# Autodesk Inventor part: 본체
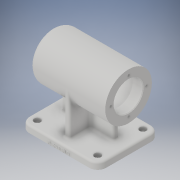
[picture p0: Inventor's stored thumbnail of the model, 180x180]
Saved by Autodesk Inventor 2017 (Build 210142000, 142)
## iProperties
Part Number: 본체
Material: 일반
Document SubType Name: Modeling
Designer: 00-00
Density: 1 g/cm^3
Appearance: 기본값
Author: 00-00
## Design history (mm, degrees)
sketch "스케치1"
  geometry: L1 (-56, 45)-(56, 45); L2 (56, 45)-(56, -45); L3 (56, -45)-(-56, -45); L4 (-56, -45)-(-56, 45); L5 (-56, 45)-(56, -45); L6 (56, 45)-(-56, -45); 1 further point
  constraints: 12 end point, 2 midpoint, 2 parallel, 1 horizontal, 1 perpendicular
  dimensions: "d0" = 112 distance of L2.end L3.end; "d1" = 90 distance of L1.end L2.end
extrude "돌출1" new body sketch "스케치1" distance "d2" = 10; taper "d3" = 0 deg
sketch "스케치2"
  geometry: L1 (0, 45)-(-74, 45); C1 r 34 at (-74, 45)
  constraints: 2 end point, 1 centre point, 1 coincident, 1 horizontal
  dimensions: "d4" = 74 distance of L1.start L1.end; "d5" = 68 diameter of C1
extrude "돌출2" join sketch "스케치2" distance "d6" = 112; taper "d7" = 0 deg
sketch "스케치3"
  geometry: L1 (38, -4)-(-38, -4); L2 (56, -45)-(56, 45) reference; L3 (-56, 45)-(-56, -45) reference; L4 (-38, -4)-(-38, 4); L5 (-38, 4)-(38, 4); L6 (38, 4)-(38, -4); L7 (-4, 34)-(4, 34); L8 (4, 34)-(4, -34); L9 (4, -34)-(-4, -34); L10 (-4, -34)-(-4, 34); L11 (-4, 34)-(4, -34); L12 (4, 34)-(-4, -34); 1 further point
  constraints: 20 end point, 3 perpendicular, 2 horizontal, 2 midpoint, 2 parallel, 1 vertical
  dimensions: "d8" = 18 distance from line of L2 L1.start; "d9" = 18 distance from line of L3 L1.end; "d10" = 4 distance from line of point (0, 0) L1; "d11" = 8 distance of L1.end L4.end; "d12" = 8 distance of L8.end L9.end; "d13" = 68 distance of L7.end L8.end
extrude "돌출3" join sketch "스케치3" stored distance "d14" = 112; taper "d15" = 0 deg
sketch "스케치4"
  geometry: C1 r 34 at (0, 0) reference; C2 r 21 at (0, 0); 1 further point
  constraints: 1 centre point, 1 coincident
  dimensions: "d16" = 42 diameter of C2
extrude "돌출4" cut sketch "스케치4" distance "d17" = 81; taper "d18" = 0 deg
node "작업 평면1"
sketch "스케치5"
  geometry: C1 r 34 at (0, 0) reference; C2 r 24 at (0, 0); 1 further point
  constraints: 1 centre point, 1 coincident
  dimensions: "d20" = 48 diameter of C2
extrude "돌출5" cut sketch "스케치5" distance "d21" = 54; taper "d22" = 0 deg
sketch "스케치6"
  geometry: C1 r 34 at (0, 0) reference; C2 r 17.5 at (0, 0); 1 further point
  constraints: 1 centre point, 1 coincident
  dimensions: "d23" = 35 diameter of C2
extrude "돌출6" cut sketch "스케치6" distance "d24" = 18; taper "d25" = 0 deg
sketch "스케치7"
  geometry: C1 r 34 at (0, 0) reference; C2 r 16 at (0, 0); 1 further point
  constraints: 1 centre point, 1 coincident
  dimensions: "d26" = 32 diameter of C2
extrude "돌출7" cut sketch "스케치7" distance "d27" = 4; taper "d28" = 0 deg
sketch "스케치8"
  geometry: C1 r 34 at (0, 0) reference; C2 r 10.5 at (0, 0); 1 further point
  constraints: 1 centre point, 1 coincident
  dimensions: "d29" = 21 diameter of C2
extrude "돌출8" cut sketch "스케치8" distance "d30" = 3; taper "d31" = 0 deg
fillet "모깎기1" dims "d32" = 10
fillet "모깎기2" dims "d33" = 12
fillet "모깎기3" dims "d34" = 3
chamfer "모따기1" distance "d35" = 1; stored, may be unused: second distance "d36" = 2, angle "d37" = 45 deg
fillet "모깎기4" dims "d38" = 3
fillet "모깎기5" dims "d39" = 0.3
fillet "모깎기6" dims "d40" = 3
sketch "스케치9"
  geometry: A1 r 9 centre (-44, 33) between (-44, 42) and (-53, 33) reference; A2 r 9 centre (44, 33) between (53, 33) and (44, 42) reference; A3 r 9 centre (-44, -33) between (-53, -33) and (-44, -42) reference; A4 r 9 centre (44, -33) between (44, -42) and (53, -33) reference; 5 further points
  constraints: 4 coincident
hole "구멍1" sketch "스케치9" at (-44, 33), (44, 33), (44, -33), (-44, -33) diameter "d41" = 5.5; stored, may be unused: countersink angle "d45" = 90 deg, drill point angle "d47" = 118 deg; dims "d42" = 6, "d43" = 9.5, "d44" = 5.4, "d46" = 8
sketch "스케치10" dims "d48" = 52
  geometry: C1 r 34 at (0, 0) reference; 6 further points
  constraints: 2 horizontal alignment, 1 coincident, 7 other
  dimensions: "d51" = 360 deg dimension on C1.centre point (-26, 0) (derived)
hole "구멍2" sketch "스케치10" at (-26, 0), (0, -26), (26, 0), (0, 26) diameter "d53" = 3.242; stored, may be unused: countersink angle "d57" = 90 deg, drill point angle "d59" = 118 deg; dims "d54" = 8, "d55" = 9.5, "d56" = 5.4, "d58" = 11
sketch "스케치11"
  geometry: L1 (100, 0)-(100, 7) reference; L2 (88, 0)-(0, 0) reference; 2 further points
  constraints: 1 other
  dimensions: "d61" = 56 distance from line of L1 point (44, 3); "d62" = 3 distance from line of L2 point (44, 3)
feature "엠보싱1" sketch "스케치11" dims "d0" = 112, "d1" = 90, "d8" = 18, "d9" = 18, "d10" = 4, "d11" = 8, "d63" = 0.5, "d64" = 0
node "솔리드1"
other parameters: "d19" = -15
